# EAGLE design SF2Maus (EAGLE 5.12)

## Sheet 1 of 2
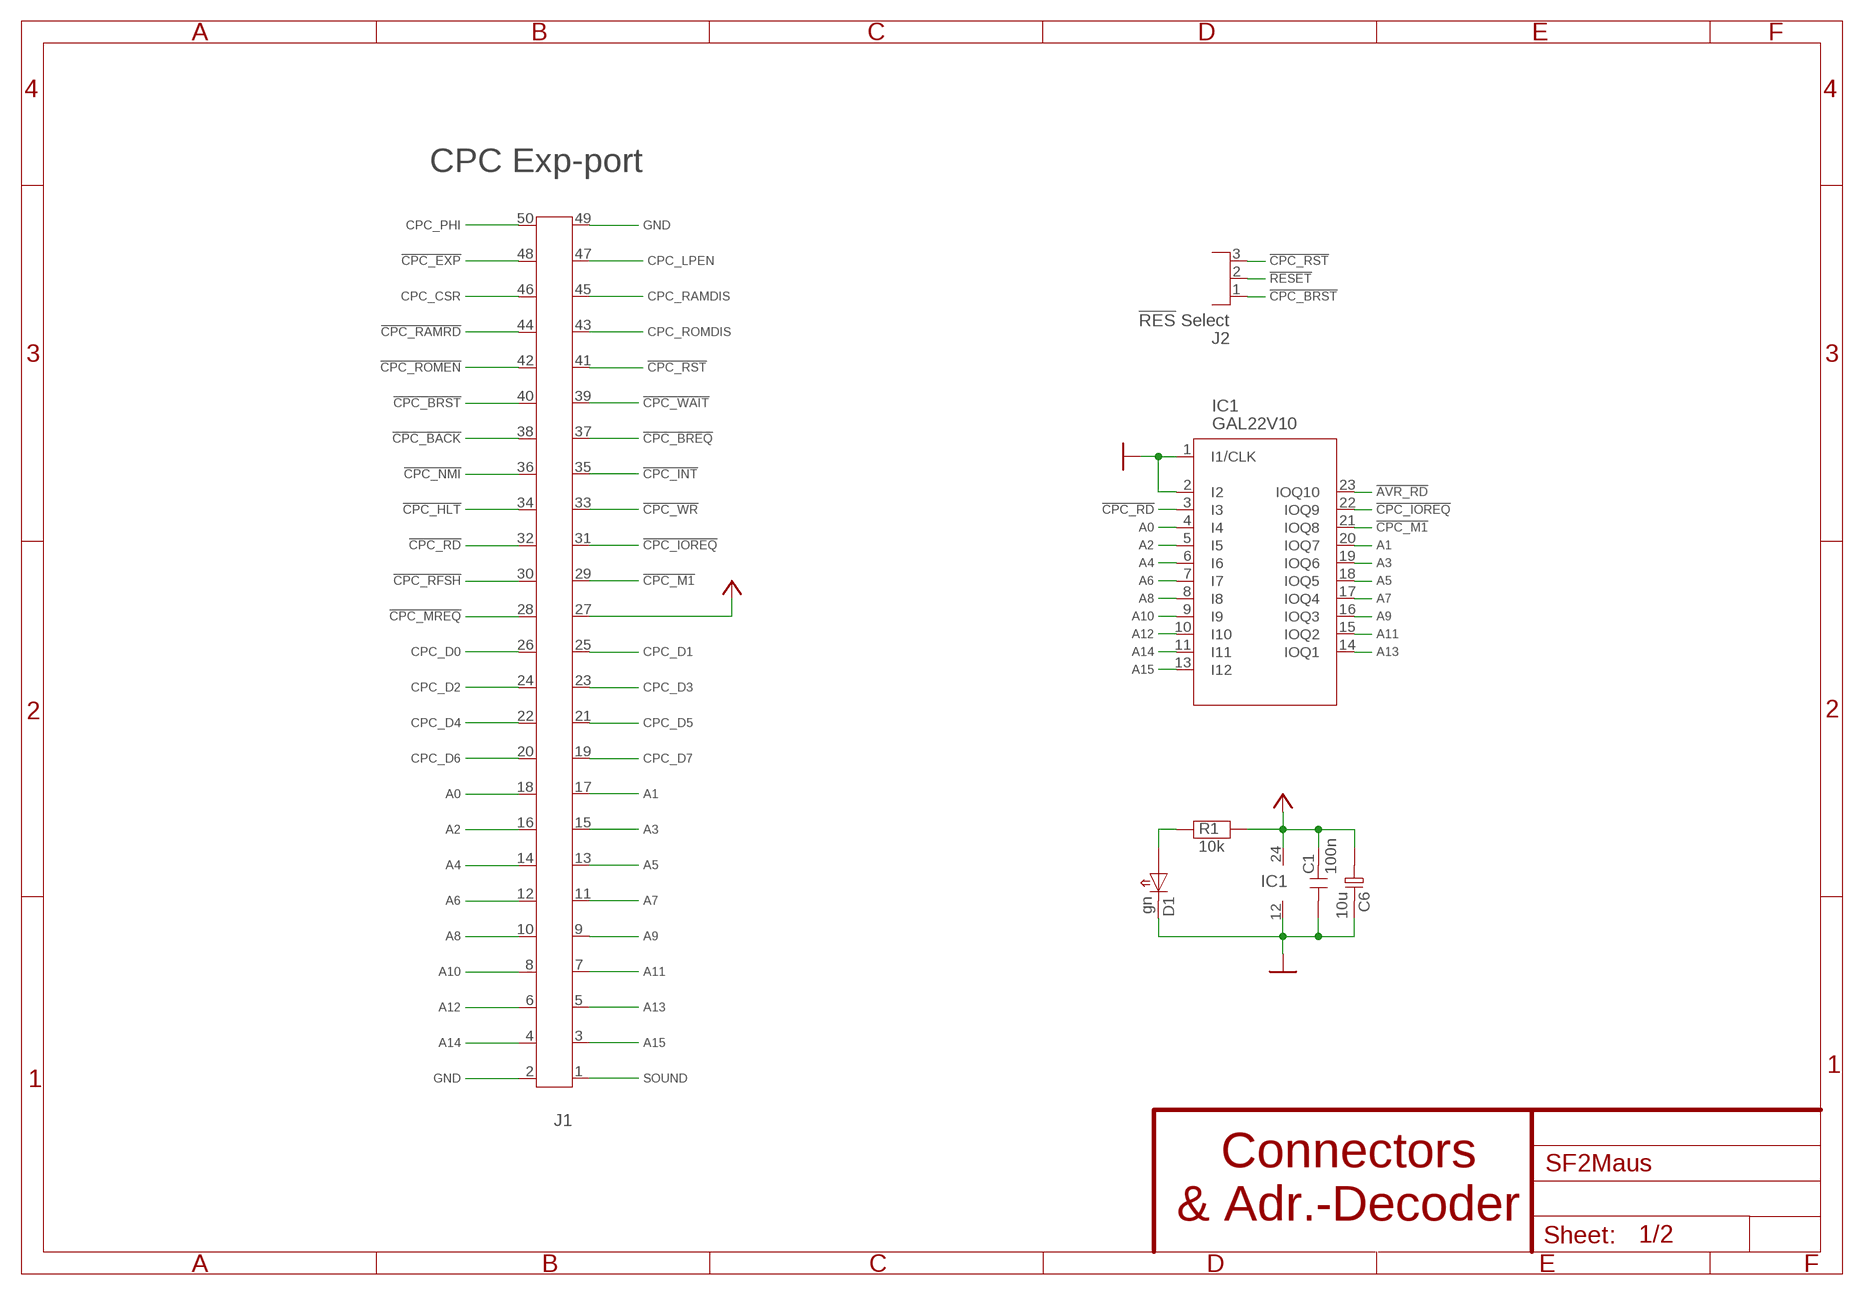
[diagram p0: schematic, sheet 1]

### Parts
C1  100n  C2  [C2]
C6  10u  ECS06  [ECS06]
D1  gn  LED3  [LED3]
IC1  GAL22V10  [DIL24S]
J1  2X25G  [2X25]
J2  !RES! Select  1X03G  [1X03]
R1  10k  R4  [R4]

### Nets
!AVR_RD: IC1.23(IOQ10) ; also sheet 2
!CPC_BACK: J1.38
!CPC_BREQ: J1.37
!CPC_BRST: J1.40 J2.1
!CPC_EXP: J1.48
!CPC_HLT: J1.34
!CPC_INT: J1.35
!CPC_IOREQ: IC1.22(IOQ9) J1.31
!CPC_M1: IC1.21(IOQ8) J1.29
!CPC_MREQ: J1.28
!CPC_NMI: J1.36
!CPC_RAMRD: J1.44
!CPC_RD: IC1.3(I3) J1.32
!CPC_RFSH: J1.30
!CPC_ROMEN: J1.42
!CPC_RST: J1.41 J2.3
!CPC_WAIT: J1.39
!CPC_WR: J1.33
!RESET: J2.2 ; also sheet 2
A0: IC1.4(I4) J1.18
A1: IC1.20(IOQ7) J1.17
A2: IC1.5(I5) J1.16
A3: IC1.19(IOQ6) J1.15
A4: IC1.6(I6) J1.14
A5: IC1.18(IOQ5) J1.13
A6: IC1.7(I7) J1.12
A7: IC1.17(IOQ4) J1.11
A8: IC1.8(I8) J1.10
A9: IC1.16(IOQ3) J1.9
A10: IC1.9(I9) J1.8
A11: IC1.15(IOQ2) J1.7
A12: IC1.10(I10) J1.6
A13: IC1.14(IOQ1) J1.5
A14: IC1.11(I11) J1.4
A15: IC1.13(I12) J1.3
CPC_CSR: J1.46
CPC_D0: J1.26 ; also sheet 2
CPC_D1: J1.25 ; also sheet 2
CPC_D2: J1.24 ; also sheet 2
CPC_D3: J1.23 ; also sheet 2
CPC_D4: J1.22 ; also sheet 2
CPC_D5: J1.21 ; also sheet 2
CPC_D6: J1.20 ; also sheet 2
CPC_D7: J1.19 ; also sheet 2
CPC_LPEN: J1.47
CPC_PHI: J1.50
CPC_RAMDIS: J1.45
CPC_ROMDIS: J1.43
GND: C1.1 C6.2(N) D1.2(K) IC1.1(I1/CLK) IC1.2(I2) IC1.12(GND) J1.2 J1.49 ; also sheet 2
N$1: D1.1(A) R1.1
SOUND: J1.1
VCC: C1.2 C6.1(P) IC1.24(VCC) J1.27 R1.2 ; also sheet 2

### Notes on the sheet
- CPC Exp-port
- Connectors
- & Adr.-Decoder

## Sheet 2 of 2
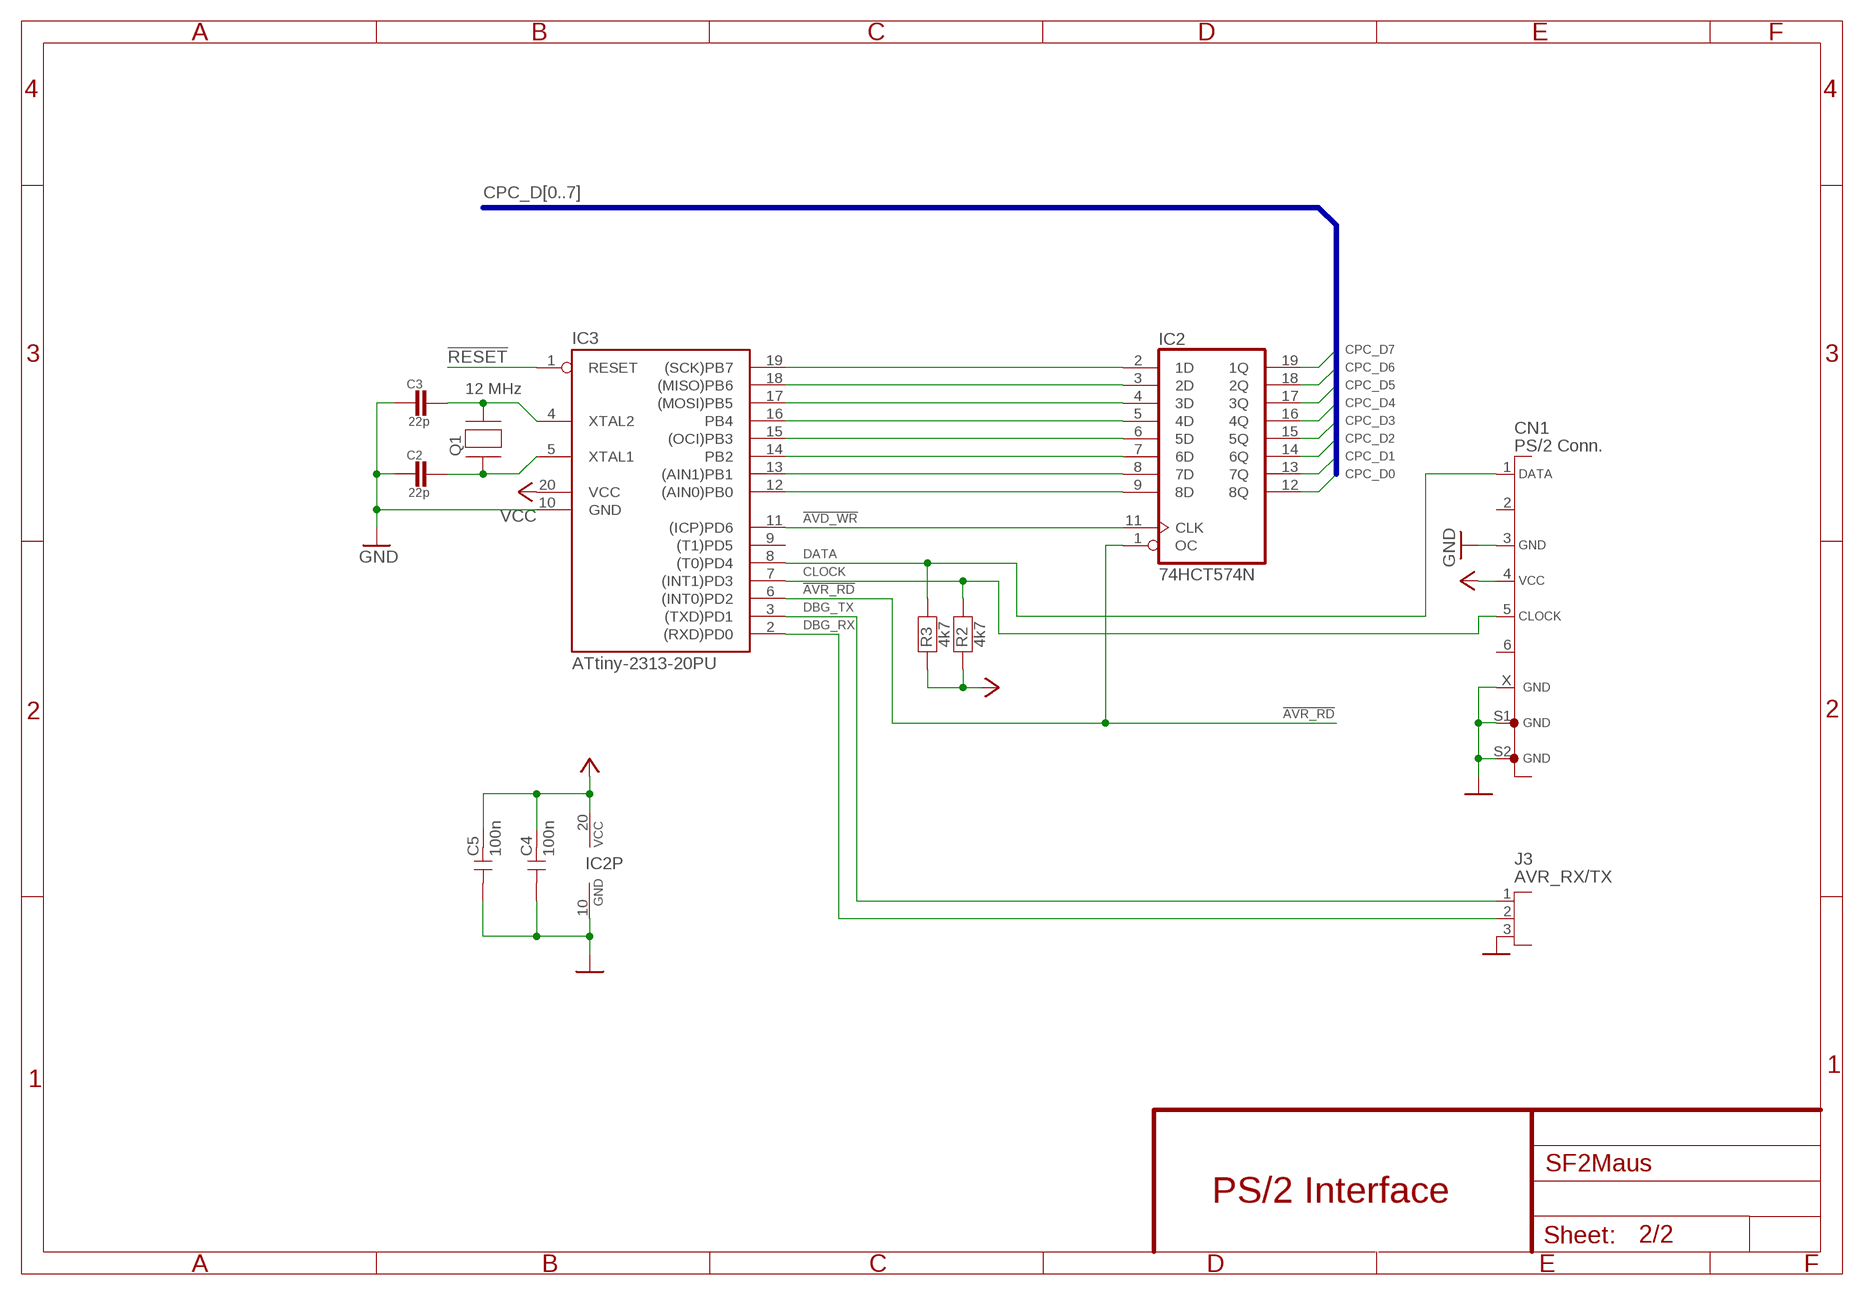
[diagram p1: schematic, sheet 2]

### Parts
C2  22p  C2  [C2]
C3  22p  C2  [C2]
C4  100n  C2  [C2]
C5  100n  C2  [C2]
CN1  PS/2 Conn.  MDIN6  [MDIN6]
IC2  74HCT574N  [DIL20]
IC3  ATtiny-2313-20PU  AT90S2313P  [DIL20]
J3  AVR_RX/TX  1X03G  [1X03]
Q1  12 MHz  Q18US  [HC18US]
R2  4k7  R4  [R4]
R3  4k7  R4  [R4]

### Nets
!AVD_WR: IC2.11(CLK) IC3.11((ICP)PD6)
!AVR_RD: IC2.1(OC) IC3.6((INT0)PD2) ; also sheet 1
!RESET: IC3.1(RESET) ; also sheet 1
CLOCK: CN1.5 IC3.7((INT1)PD3) R2.2
CPC_D0: IC2.12(8Q) ; also sheet 1
CPC_D1: IC2.13(7Q) ; also sheet 1
CPC_D2: IC2.14(6Q) ; also sheet 1
CPC_D3: IC2.15(5Q) ; also sheet 1
CPC_D4: IC2.16(4Q) ; also sheet 1
CPC_D5: IC2.17(3Q) ; also sheet 1
CPC_D6: IC2.18(2Q) ; also sheet 1
CPC_D7: IC2.19(1Q) ; also sheet 1
DATA: CN1.1 IC3.8((T0)PD4) R3.2
DBG_RX: IC3.2((RXD)PD0) J3.2
DBG_TX: IC3.3((TXD)PD1) J3.1
GND: C2.P$1 C3.P$1 C4.1 C5.1 CN1.3 CN1.S1 CN1.S2 CN1.X IC2.10(GND) IC3.10(GND) J3.3 ; also sheet 1
N$2: C2.P$2 IC3.5(XTAL1) Q1.1
N$3: C3.P$2 IC3.4(XTAL2) Q1.2
N$20: IC2.2(1D) IC3.19((SCK)PB7)
N$21: IC2.3(2D) IC3.18((MISO)PB6)
N$23: IC2.4(3D) IC3.17((MOSI)PB5)
N$24: IC2.5(4D) IC3.16(PB4)
N$27: IC2.6(5D) IC3.15((OCI)PB3)
N$28: IC2.7(6D) IC3.14(PB2)
N$29: IC2.8(7D) IC3.13((AIN1)PB1)
N$30: IC2.9(8D) IC3.12((AIN0)PB0)
VCC: C4.2 C5.2 CN1.4 IC2.20(VCC) IC3.20(VCC) R2.1 R3.1 ; also sheet 1
Unconnected: CN1.2 CN1.6 IC3.9((T1)PD5)

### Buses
CPC_D[0..7]

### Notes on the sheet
- PS/2 Interface

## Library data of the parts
C1 C4 C5 = STD:C: Ungepolte Kondensatoren in verschiedenen Ausführungen
C2 C3 = mylib:C2
C6 = STD:EC: Elkos in allen Variationen
CN1 = STECK:MDIN6: Mini-DIN Buchse 6-polig 90° mit Schirm
D1 = STD:LED: LEDs in verschiedenen Bauformen
IC1 = DIGITAL:GAL22V10
IC2 = 74xx:74*574: 8-bit D type FLIP FLOP bus driver
IC3 = atmel:AT90S2313: MICROCONTROLLER 2 Kbytes FLASH 128 bytes SRAM 128 bytes EEPROM UART
J1 = PINHEAD:2X25
J2 J3 = PINHEAD:1X03
Q1 = STD:Q: Quarze 2-pol.
R1-R3 = STD:R: Widerstände, verschiedene Bauformen

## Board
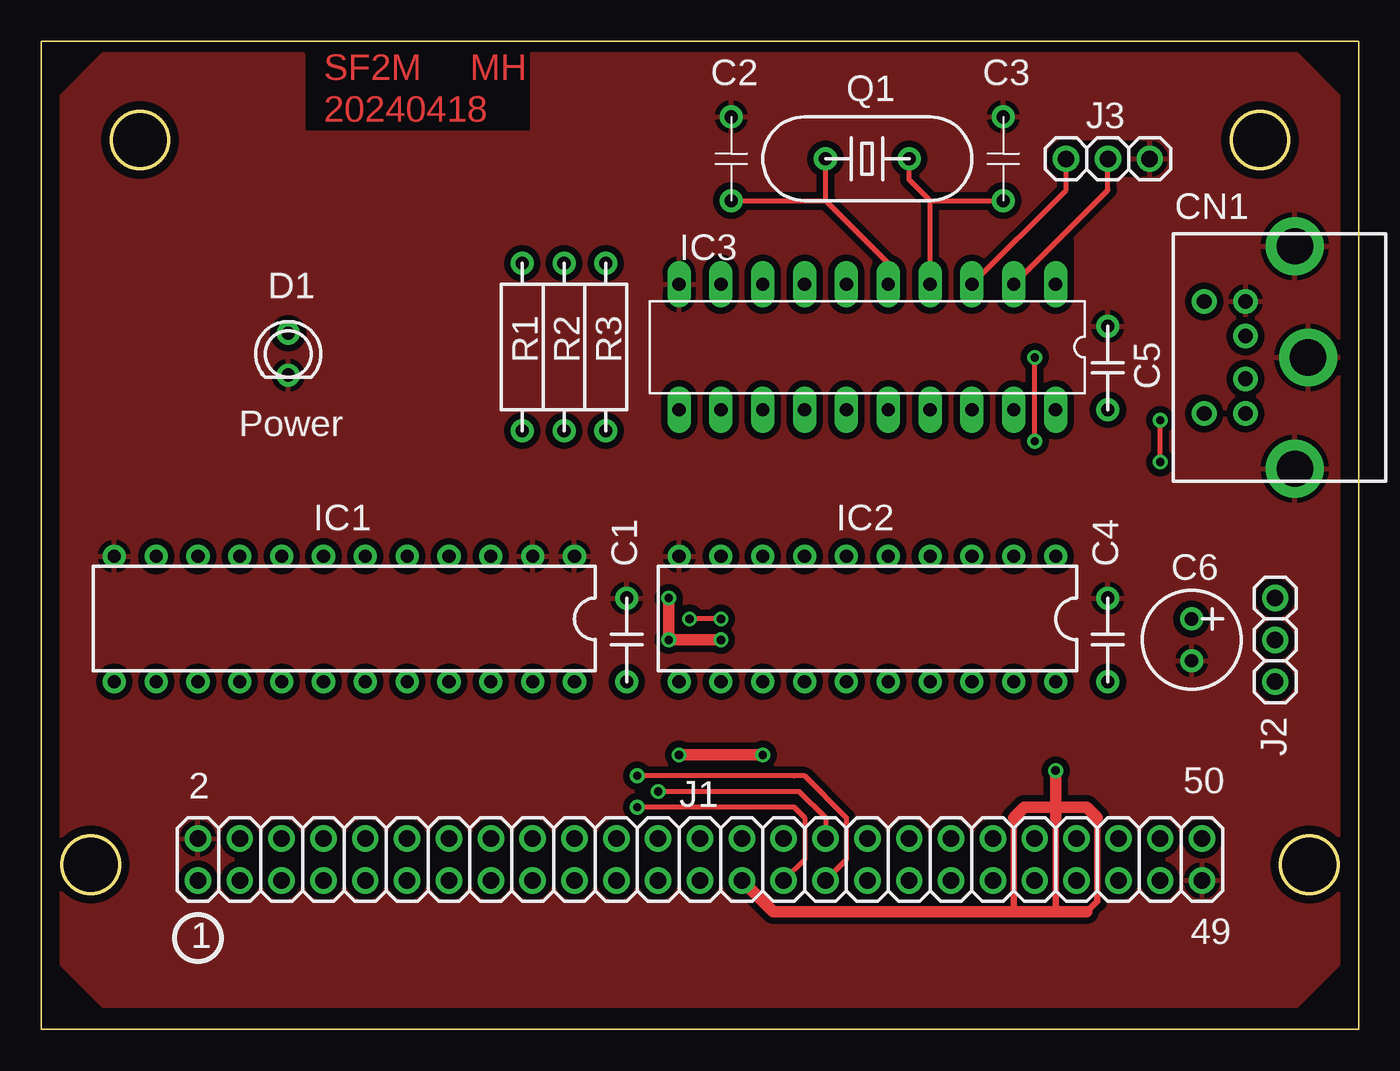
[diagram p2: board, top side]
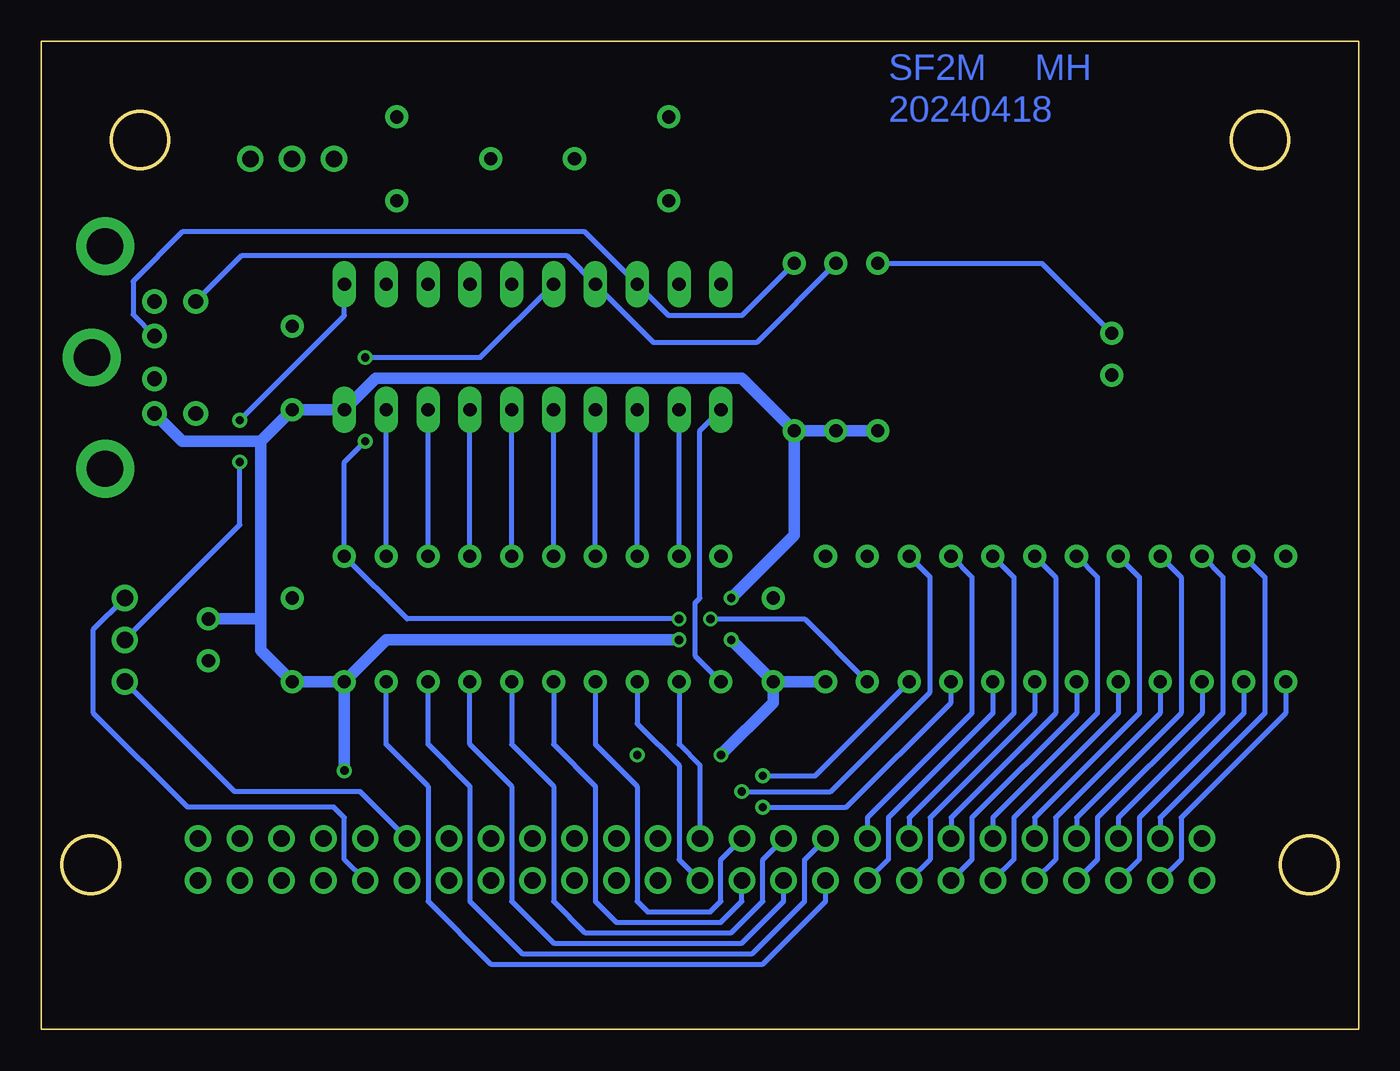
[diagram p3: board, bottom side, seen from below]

Size 80 x 60 mm. Coordinates in mm from the lower left corner, seen from the top.
Outline: 0,0 80,0 80,60 0,60 0,0
Copper layers (1*16): Top 0.035mm / dielectric 1.5mm / Bottom 0.035mm
Design rules "SMD-2-Round": minimum track width 0.15mm, minimum drill 0.5mm, track to track 0.2mm, track to pad 0.2mm, pad to pad 0.3mm, via to via 0.3mm, smd to smd 0.2mm, copper to edge 0.5mm, drill to drill 0.5mm, minimum pad ring 0.3mm, minimum via ring 0.2mm, stop-mask expansion 0.03mm, vias tented up to drill 0mil, thermal gap 0.3mm
tRestrict: 6 lines
Milling: 4 lines

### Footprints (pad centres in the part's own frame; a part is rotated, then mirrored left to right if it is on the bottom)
C2 = drill 0.8 pad 1.4 round: 1 -2.54,0; 2 2.54,0
C2' = drill 0.8 round: P$1 -2.54,0; P$2 2.54,0
ECS06 = drill 0.8 pad 1.4 round: 1 -1.27,0; 2 1.27,0
MDIN6 = drill 0.9 pad 1.5 round: 1 1.3,0; 2 -1.3,0; 3 3.4,0; 4 -3.4,0; 5 3.4,2.5; 6 -3.4,2.5 | drill 2.2 pad 3 round: S1 -6.75,-3; S2 6.75,-3; X 0,-3.8
LED3 = drill 0.8 pad 1.4 round: 1 -1.27,0; 2 1.27,0
DIL24S = drill 0.8 pad 1.4 round: 1 -13.97,-3.81; 2 -11.43,-3.81; 3 -8.89,-3.81; 4 -6.35,-3.81; 5 -3.81,-3.81; 6 -1.27,-3.81; 7 1.27,-3.81; 8 3.81,-3.81; 9 6.35,-3.81; 10 8.89,-3.81; 11 11.43,-3.81; 12 13.97,-3.81; 13 13.97,3.81; 14 11.43,3.81; 15 8.89,3.81; 16 6.35,3.81; 17 3.81,3.81; 18 1.27,3.81; 19 -1.27,3.81; 20 -3.81,3.81; 21 -6.35,3.81; 22 -8.89,3.81; 23 -11.43,3.81; 24 -13.97,3.81
DIL20 = drill 0.8 pad 1.4 round: 1 -11.43,-3.81; 2 -8.89,-3.81; 3 -6.35,-3.81; 4 -3.81,-3.81; 5 -1.27,-3.81; 6 1.27,-3.81; 7 3.81,-3.81; 8 6.35,-3.81; 9 8.89,-3.81; 10 11.43,-3.81; 11 11.43,3.81; 12 8.89,3.81; 13 6.35,3.81; 14 3.81,3.81; 15 1.27,3.81; 16 -1.27,3.81; 17 -3.81,3.81; 18 -6.35,3.81; 19 -8.89,3.81; 20 -11.43,3.81
DIL20' = drill 0.813 long: 1 -11.43,-3.81; 2 -8.89,-3.81; 3 -6.35,-3.81; 4 -3.81,-3.81; 5 -1.27,-3.81; 6 1.27,-3.81; 7 3.81,-3.81; 8 6.35,-3.81; 9 8.89,-3.81; 10 11.43,-3.81; 11 11.43,3.81; 12 8.89,3.81; 13 6.35,3.81; 14 3.81,3.81; 15 1.27,3.81; 16 -1.27,3.81; 17 -3.81,3.81; 18 -6.35,3.81; 19 -8.89,3.81; 20 -11.43,3.81
2X25 = drill 1 pad 1.6 round: 1 -30.48,-1.27; 2 -30.48,1.27; 3 -27.94,-1.27; 4 -27.94,1.27; 5 -25.4,-1.27; 6 -25.4,1.27; 7 -22.86,-1.27; 8 -22.86,1.27; 9 -20.32,-1.27; 10 -20.32,1.27; 11 -17.78,-1.27; 12 -17.78,1.27; 13 -15.24,-1.27; 14 -15.24,1.27; 15 -12.7,-1.27; 16 -12.7,1.27; 17 -10.16,-1.27; 18 -10.16,1.27; 19 -7.62,-1.27; 20 -7.62,1.27; 21 -5.08,-1.27; 22 -5.08,1.27; 23 -2.54,-1.27; 24 -2.54,1.27; 25 0,-1.27; 26 0,1.27; 27 2.54,-1.27; 28 2.54,1.27; 29 5.08,-1.27; 30 5.08,1.27; 31 7.62,-1.27; 32 7.62,1.27; 33 10.16,-1.27; 34 10.16,1.27; 35 12.7,-1.27; 36 12.7,1.27; 37 15.24,-1.27; 38 15.24,1.27; 39 17.78,-1.27; 40 17.78,1.27; 41 20.32,-1.27; 42 20.32,1.27; 43 22.86,-1.27; 44 22.86,1.27; 45 25.4,-1.27; 46 25.4,1.27; 47 27.94,-1.27; 48 27.94,1.27; 49 30.48,-1.27; 50 30.48,1.27
1X03 = drill 1 pad 1.6 round: 1 -2.54,0; 2 0,0; 3 2.54,0
HC18US = drill 0.8 pad 1.4 round: 1 -2.54,0; 2 2.54,0
R4 = drill 0.8 pad 1.4 round: 1 -5.08,0; 2 5.08,0
HOLE35DIM = hole 3.5: 0,0

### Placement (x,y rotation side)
C1  35.55,23.65 270 top
C2  22p  [C2']  41.91,52.86 270 top
C3  22p  [C2']  58.41,52.86 270 top
C4  64.77,23.65 270 top
C5  64.77,40.16 270 top
C6  69.84,23.65 270 top
CN1  73.12,40.8 90 top
D1  15,41 270 top
IC1  18.41,24.92 180 top
IC2  50.16,24.92 180 top
IC3  ATtiny-2313-20PU  [DIL20']  50.16,41.43 180 top
J1  40,10.32 0 top
J2  74.92,23.65 90 top
J3  64.77,52.86 0 top
Q1  50.16,52.86 0 top
R1  29.2,41.43 270 top
R2  31.74,41.43 90 top
R3  34.28,41.43 90 top
U$1  [HOLE35DIM]  74,54 0 top
U$3  [HOLE35DIM]  6,54 0 top
U$4  [DRAWING]  not placed on the board
U$5  [HOLE35DIM]  3,10 0 top
U$6  [HOLE35DIM]  77,10 0 top

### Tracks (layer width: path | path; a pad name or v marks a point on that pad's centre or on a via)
!AVD_WR
  Bottom 0.3: IC3.11 40,36.35 40,26.19 40.32,25.87 40.32,22.7 IC2.11
!AVR_RD  (via drill 0.5 pad 0.9)
  Top 0.3: v41.27,24.92 v39.37,24.92 | v60.32,35.72 v60.32,40.8
  Bottom 0.3: v60.32,35.72 61.59,34.45 IC2.1 57.78,24.92 v41.27,24.92 | IC3.6 53.34,40.8 v60.32,40.8 | IC1.23 33.65,24.92 v39.37,24.92
!CPC_BRST
  Bottom 0.3: J2.1 68.26,14.44 60.64,14.44 J1.40
!CPC_IOREQ  (via drill 0.5 pad 0.9)
  Top 0.3: v36.19,15.39 45.72,15.39 46.35,15.39 48.89,12.86 48.89,10.32 J1.31
  Bottom 0.3: v36.19,15.39 33.02,15.39 IC1.22
!CPC_M1  (via drill 0.5 pad 0.9)
  Top 0.3: v36.19,13.49 45.72,13.49 46.35,12.86 46.35,10.32 J1.29
  Bottom 0.3: v36.19,13.49 31.11,13.49 24.76,19.84 IC1.21
!CPC_RD  (via drill 0.5 pad 0.9)
  Top 0.3: v37.46,14.44 44.76,14.44 45.08,14.44 46.03,14.44 47.62,12.86 J1.32
  Bottom 0.3: v37.46,14.44 32.06,14.44 26.03,20.48 26.03,27.46 IC1.3
!CPC_RST
  Bottom 0.3: J2.3 76.83,24.29 76.83,19.2 71.11,13.49 62.23,13.49 61.59,12.86 61.59,10.32 J1.41
!RESET  (via drill 0.5 pad 0.9)
  Top 0.3: v67.94,34.45 v67.94,36.98
  Bottom 0.3: v67.94,36.98 61.59,43.34 IC3.1 | J2.2 67.94,30.64 v67.94,34.45
A0
  Bottom 0.3: J1.18 29.84,12.86 23.49,19.2 23.49,27.46 IC1.4
A1
  Bottom 0.3: J1.17 28.57,10.32 28.57,12.86 22.22,19.2 IC1.20
A2
  Bottom 0.3: J1.16 27.3,12.86 20.95,19.2 20.95,27.46 IC1.5
A3
  Bottom 0.3: J1.15 26.03,10.32 26.03,12.86 19.68,19.2 IC1.19
A4
  Bottom 0.3: J1.14 24.76,12.86 18.41,19.2 18.41,27.46 IC1.6
A5
  Bottom 0.3: J1.13 23.49,10.32 23.49,12.86 17.14,19.2 IC1.18
A6
  Bottom 0.3: J1.12 22.22,12.86 15.87,19.2 15.87,27.46 IC1.7
A7
  Bottom 0.3: J1.11 20.95,10.32 20.95,12.86 14.6,19.2 IC1.17
A8
  Bottom 0.3: J1.10 19.68,12.86 13.33,19.2 13.33,27.46 IC1.8
A9
  Bottom 0.3: J1.9 18.41,10.32 18.41,12.86 12.06,19.2 IC1.16
A10
  Bottom 0.3: J1.8 17.14,12.86 10.79,19.2 10.79,27.46 IC1.9
A11
  Bottom 0.3: J1.7 15.87,10.32 15.87,12.86 9.52,19.2 IC1.15
A12
  Bottom 0.3: J1.6 14.6,12.86 8.25,19.2 8.25,27.46 IC1.10
A13
  Bottom 0.3: J1.5 13.33,10.32 13.33,12.86 6.98,19.2 IC1.14
A14
  Bottom 0.3: J1.4 12.06,12.86 5.71,19.2 5.71,27.46 IC1.11
A15
  Bottom 0.3: J1.3 10.79,10.32 10.79,12.86 4.44,19.2 IC1.13
CLOCK
  Bottom 0.3: R2.2 36.55,41.7 42.81,41.7 IC3.7 48.07,46.96 67.85,46.96 CN1.5
CPC_D0
  Bottom 0.3: IC2.12 41.27,17.3 40,16.03 J1.26
CPC_D1
  Bottom 0.3: IC2.13 43.81,18.57 41.27,16.03 41.27,10.32 J1.25
CPC_D2
  Bottom 0.3: IC2.14 46.35,17.3 43.81,14.76 43.81,7.77 43.17,7.14 39.37,7.14 38.73,7.77 38.73,10.32 J1.24
CPC_D3
  Bottom 0.3: IC2.15 48.89,17.3 46.35,14.76 46.35,7.77 45.08,6.5 38.73,6.5 37.46,7.77 J1.23
CPC_D4
  Bottom 0.3: IC2.16 51.43,17.3 48.89,14.76 48.89,7.77 46.98,5.87 38.09,5.87 36.19,7.77 36.19,10.32 J1.22
CPC_D5
  Bottom 0.3: IC2.17 53.97,17.3 51.43,14.76 51.43,7.77 48.89,5.23 37.46,5.23 34.92,7.77 J1.21
CPC_D6
  Bottom 0.3: IC2.18 56.51,17.3 53.97,14.76 53.97,7.77 50.8,4.6 36.83,4.6 33.65,7.77 33.65,10.32 J1.20
CPC_D7
  Bottom 0.3: IC2.19 59.05,17.3 56.51,14.76 56.51,7.77 52.7,3.96 36.19,3.96 32.38,7.77 J1.19
DATA
  Bottom 0.3: R3.2 37.46,43.34 41.91,43.34 IC3.8 46.98,48.41 71.43,48.41 74.42,45.42 74.42,43.4 CN1.1
DBG_RX
  Top 0.3: IC3.2 64.77,50.95 J3.2
DBG_TX
  Top 0.3: J3.1 62.23,50.95 IC3.3
GND
  pour Top (isolate 0.4): 1.27,56.67 3.8,59.21 15.87,59.21 15.87,54.45 29.84,54.45 29.84,59.21 76.19,59.21 78.73,56.67 78.73,3.96 76.19,1.43 3.8,1.43 1.27,3.96
N$1
  Bottom 0.3: R1.1 19.24,46.51 D1.1
N$2
  Top 0.3: IC3.5 51.43,46.51 47.62,50.32 | C2.P$2 47.62,50.32 | 47.62,50.32 Q1.1
N$3
  Top 0.3: Q1.2 52.7,51.59 53.97,50.32 | IC3.4 53.97,50.32 | 53.97,50.32 C3.P$2
N$20
  Bottom 0.3: IC2.2 IC3.19
N$21
  Bottom 0.3: IC2.3 IC3.18
N$23
  Bottom 0.3: IC2.4 IC3.17
N$24
  Bottom 0.3: IC2.5 IC3.16
N$27
  Bottom 0.3: IC2.6 IC3.15
N$28
  Bottom 0.3: IC2.7 IC3.14
N$29
  Bottom 0.3: IC2.8 IC3.13
N$30
  Bottom 0.3: IC2.9 IC3.12
VCC  (via drill 0.5 pad 0.9)
  Top 0.4: 63.5,7.14 64.13,7.77 64.13,12.86 | 61.59,12.86 61.59,7.14 | 59.05,12.86 59.05,7.14
  Top 0.7: v41.27,23.65 v38.09,23.65 v38.09,26.19 | v38.73,16.66 v43.81,16.66 | J1.27 44.45,7.14 59.05,7.14 61.59,7.14 63.5,7.14 | 61.59,13.49 59.69,13.49 59.05,12.86 | 61.59,13.49 v61.59,15.71 61.59,12.86 | 61.59,13.49 63.5,13.49 64.13,12.86
  Bottom 0.7: 66.67,35.72 C5.2 IC3.20 59.69,39.52 37.46,39.52 R3.1 | 66.67,35.72 66.67,24.92 | 66.67,24.92 66.67,23.02 C4.2 IC2.20 | C1.2 IC1.24 | v38.09,23.65 C1.2 | v41.27,23.65 59.05,23.65 IC2.20 | C1.2 35.55,19.84 v38.73,16.66 | R3.1 R2.1 R1.2 | v38.09,26.19 34.28,30 R3.1 | 66.67,24.92 C6.1 | 66.67,35.72 71.44,35.72 CN1.4 | IC2.20 v61.59,15.71

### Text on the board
Top: SF2M | MH | 20240418
Bottom: MH | SF2M | 20240418
tNames: Power | 2 | 50 | 49 | 1
Measures: 1,6 | 25 | 0 | 30 | 11 | 11 | 0 | 0 | 30 | 40 | 0 | 40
